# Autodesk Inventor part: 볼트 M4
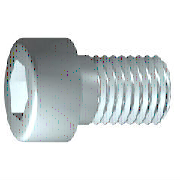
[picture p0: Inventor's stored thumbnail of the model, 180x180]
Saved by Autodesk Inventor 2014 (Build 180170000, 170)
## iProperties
IsCustomPart: 1
Created: 2012-02
Part Number: 볼트 M4
Material: 강철, 연강
Description: 6각머리 태핑 나사
Document SubType Name: Modeling
Standard: KS B 1003
Designer: mduedu
Standards Organization: KS
Language: ko-KR
Size Designation: M 4 x 10
Categories: <MemberInstance><Categories><Category DisplayName="조임쇠" InternalName="e4da775c-781d-43d5-af7c-5136215cf5a6" Mnemonic="FSTN"><Category DisplayName="볼트" InternalN
Density: 7.86 g/cm^3
Appearance: 강철
Mass: 2.0371 g
Surface Area: 3.0572 cm^2
Volume: 0.259174 cm^3
Author: mduedu
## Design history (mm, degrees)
sketch "스케치1"
  geometry: L1 (-1, 0)-(10, 0); L2 (10, 0)-(10, 2); L3 (10, 2)-(1.75, 2); L4 (1.75, 2)-(1.32, 2); L5 (1.32, 2)-(0, 2); L6 (0, 2)-(0, 3.5); L7 (0, 3.5)-(-4, 3.5); L8 (-4, 3.5)-(-4, 1.732); L9 (-4, 1.732)-(-2, 1.732); L10 (-2, 1.732)-(-1, 0); L11 (-6.8, 0)-(12.8, 0) reference; L12 (0, -0.7)-(0, 4.2) reference; L13 (1.75, 2)-(0, 2)
  constraints: 22 end point, 6 parallel, 2 collinear, 2 perpendicular, 1 horizontal, 1 point on line
  dimensions: "d1" = 8.25 distance from line of L3.end L2 (= GEL); "d2" = 0.42952 distance of L4.end L3.end (computed from GAL); "d3" = 4 distance between parallel lines of L8 L6 (= KOH); "d4" = 2 distance of L8.end L9.end (= INTI); "d5" = 60 deg angle of L10 L1; "d6" = 4 diameter of L3 L1 (= GD); "d7" = 4 diameter of L5 L1 (= BDM); "d8" = 3.4641 diameter of L9 L1 (= 1.1547 x SW); "d9" = 7 diameter of L7 L1 (= KOD); "d26" = 10 distance between parallel lines of L12 L2 (= NLG)
revolve "본체" sketch "스케치1" stored, may be unused: angle "d10" = 90 deg
sketch "스케치2"
  geometry: L1 (0, -4.9)-(0, 4.9) reference; L2 (-4.9, 0)-(4.9, 0) reference; L3 (1.732, 0)-(0.866, -1.5); L4 (0.866, -1.5)-(-0.866, -1.5); L5 (-0.866, -1.5)-(-1.732, 0); L6 (-1.732, 0)-(-0.866, 1.5); L7 (-0.866, 1.5)-(0.866, 1.5); L8 (0.866, 1.5)-(1.732, 0); 2 further points
  constraints: 12 end point, 1 coincident, 1 horizontal alignment, 1 point on line, 12 other
extrude "슬롯" join sketch "스케치2" stored distance "d11" = 10; taper "d12" = 0 deg
workplane "Work Plane1"
fillet "Fillet2" dims "d30" = 0.1 (= R)
body "Solid1"
fillet "모깎기1" dims "d17" = 0.4 (= RR)
feature "스레드" dims "d13" = 8.25 (= GEL), "d14" = 0
chamfer "모따기1" distance "d15" = 0.42941 (= -0.5 x SPD + 0.5 x GD); stored, may be unused: second distance "d16" = 0.42941 (= GUL), angle "d27" = 45 deg
other parameters: "GD" = 4 (= NND) [user parameter; used in 2 equation terms], "NLG" = 10 [user parameter; used in 1 equation term], "GEL" = 8.25 [user parameter; used in 2 equation terms], "KOD" = 7 [user parameter; used in 1 equation term], "KOH" = 4 [user parameter; used in 1 equation term], "INTI" = 2 [user parameter; used in 1 equation term], "GAL" = 0.42941 (= 0.61345 x PTC) [user parameter; used in 1 equation term], "GUL" = 0.42941 (= 0.61345 x PTC) [user parameter; used in 1 equation term], "BDM" = 4 (= NND) [user parameter; used in 1 equation term], "SW" = 3 [user parameter; used in 2 equation terms], "RR" = 0.4 [user parameter; used in 1 equation term], "SPD" = 3.14117 (= NND - 1.2269 x PTC) [user parameter; used in 1 equation term], "d19" = 0, "d28" = 0, "d29" = 0, "R" = 0.1 [user parameter; used in 1 equation term], "PHH" = 0.2 [user parameter], "GD1" = 3.14117 (= THREADDIA - 1.2269 x PTC) [user parameter], "THREADDIA" = 4 [user parameter; used in 1 equation term], "FAWI" = 45 deg [user parameter], "TPU" = 14.28571 (computed from PTC) [user parameter], "PTC" = 0.7 [user parameter; used in 5 equation terms], "NND" = 4 [user parameter; used in 3 equation terms], "TOA" = 30 deg [user parameter], "E0" = 3.465 (= 1.155 x SW) [user parameter]
